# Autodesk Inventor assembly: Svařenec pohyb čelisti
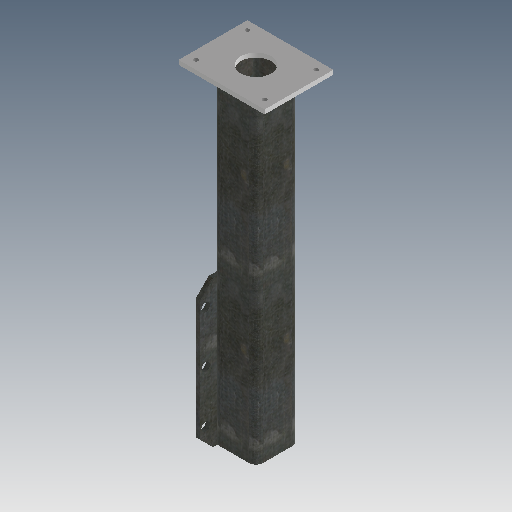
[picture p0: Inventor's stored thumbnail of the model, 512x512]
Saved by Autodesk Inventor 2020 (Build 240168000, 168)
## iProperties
Created: 2025-03
Part Number: Svařenec pohyb čelisti
Document SubType Name: Assembly
Designer: doma
Mass: 2640.56 g
Surface Area: 1802.71 cm^2
Volume: 366.752 cm^3
Density: 7.19984 g/cm^3
Author: doma
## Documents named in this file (4)
- C:\Users\doma\Desktop\Pásovka záloha\Workgroups\NotInProject\Svařenec pohyb čelisti.iam
- C:\Users\doma\Desktop\Pásovka záloha\Workgroups\NotInProject\Jekl 4.ipt
- C:\Users\doma\Desktop\Pásovka záloha\Workgroups\NotInProject\Podstava.ipt
- C:\Users\doma\Desktop\Pásovka záloha\Workgroups\NotInProject\Příruba svěrák.ipt
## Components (3 placed, 3 different names)
1. Jekl 4:1 — Proti sobě:1, Stejný směr:2, Stejný směr:3, Stejný směr:4, Stejný směr:5, Proti sobě:2
2. Podstava:1 — Proti sobě:1, Stejný směr:2, Stejný směr:5
3. Příruba svěrák:2 — Stejný směr:3, Stejný směr:4, Proti sobě:2
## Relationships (6: Flush 4, Mate 2)
- Proti sobě:1 [Mate]: Jekl 4:1 ↔ Podstava:1
- Stejný směr:2 [Flush]: Jekl 4:1 ↔ Podstava:1
- Stejný směr:3 [Flush]: Jekl 4:1 ↔ Příruba svěrák:2
- Stejný směr:4 [Flush]: Jekl 4:1 ↔ Příruba svěrák:2
- Stejný směr:5 [Flush]: Jekl 4:1 ↔ Podstava:1
- Proti sobě:2 [Mate]: Jekl 4:1 ↔ Příruba svěrák:2
